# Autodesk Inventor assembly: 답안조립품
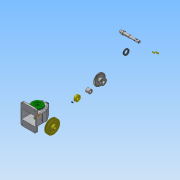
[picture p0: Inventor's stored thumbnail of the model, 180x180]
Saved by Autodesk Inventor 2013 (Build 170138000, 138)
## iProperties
Created: 2016-12
Part Number: 답안조립품
Document SubType Name: Assembly
Designer: Administrator
Author: Administrator
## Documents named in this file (15)
- C:\Users\Administrator\Desktop\461208V1015\답안조립품.iam
- C:\Users\Administrator\Desktop\461208V1015\본체.ipt
- C:\Users\Administrator\Desktop\461208V1015\V-벨트풀리.ipt
- C:\Users\Administrator\Desktop\461208V1015\뒤커버.ipt
- C:\Users\Administrator\Desktop\461208V1015\멈춤나사 - M4x10.ipt
- C:\Users\Administrator\Desktop\461208V1015\베어링 6203.ipt
- C:\Users\Administrator\Desktop\461208V1015\볼트 M3 x 8.ipt
- C:\Users\Administrator\Desktop\461208V1015\볼트 M3 x 10.ipt
- C:\Users\Administrator\Desktop\461208V1015\부시.ipt
- C:\Users\Administrator\Desktop\461208V1015\스퍼기어.ipt
- C:\Users\Administrator\Desktop\461208V1015\앞커버.ipt
- C:\Users\Administrator\Desktop\461208V1015\오일씰 28 40 8.ipt
- C:\Users\Administrator\Desktop\461208V1015\축.ipt
- C:\Users\Administrator\Desktop\461208V1015\키 - 5 x 5 x 18.ipt
- C:\Users\Administrator\Desktop\461208V1015\키 - 6 x 6 x 22.ipt
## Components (9 placed, 3 different names)
1. V-벨트풀리:1
2. ISO 4762 M3 x 8:1
3. ISO 4762 M3 x 8:2
4. ISO 4762 M3 x 8:3
5. ISO 4762 M3 x 8:4
6. ISO 4762 M3 x 10:1
7. ISO 4762 M3 x 10:2
8. ISO 4762 M3 x 10:3
9. ISO 4762 M3 x 10:4
